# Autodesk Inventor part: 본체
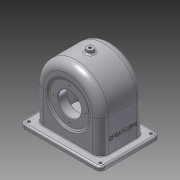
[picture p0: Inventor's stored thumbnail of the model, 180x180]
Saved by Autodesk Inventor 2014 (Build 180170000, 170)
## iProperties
Created: 2016-01
Part Number: 본체
Material: 알루미늄 6061
Document SubType Name: 판금
Designer: SCD-A15
Density: 2.71 g/cm^3
Appearance: 알루미늄 - 평지
Sheet Metal Rule: 기본값
Mass: 912.796 g
Surface Area: 1098.08 cm^2
Volume: 336.825 cm^3
Author: SCD-A15
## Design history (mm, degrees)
sketch "스케치1"
  geometry: L1 (-70, 52)-(70, 52); L2 (70, 52)-(70, -52); L3 (70, -52)-(-70, -52); L4 (-70, -52)-(-70, 52); 3 further points
  constraints: 8 end point, 2 midpoint, 2 parallel, 1 horizontal, 1 horizontal alignment, 1 perpendicular, 1 vertical alignment
  dimensions: "d0" = 140 distance of L1.start L1.end; "d1" = 104 distance of L1.end L2.end
extrude "돌출1" new body sketch "스케치1" distance "d2" = 7; taper "d3" = 0 deg
node "작업 평면1"
sketch "스케치3"
  geometry: L1 (-43, 38.5)-(43, 38.5); L2 (57, 24.5)-(57, -24.5); L3 (43, -38.5)-(-43, -38.5); L4 (-57, -24.5)-(-57, 24.5); L5 (-42, 33.5)-(42, 33.5); L6 (51, 24.5)-(51, -24.5); L7 (42, -33.5)-(-42, -33.5); L8 (-51, -24.5)-(-51, 24.5); L9 (0, 33.5)-(0, -33.5); L10 (0, 38.5)-(0, 33.5); L11 (0, -33.5)-(0, -38.5); A1 r 9 centre (-42, 24.5) between (-42, 33.5) and (-51, 24.5); A2 r 9 centre (-42, -24.5) between (-51, -24.5) and (-42, -33.5); A3 r 9 centre (42, -24.5) between (42, -33.5) and (51, -24.5); A4 r 9 centre (42, 24.5) between (51, 24.5) and (42, 33.5); A5 r 14 centre (-43, 24.5) between (-43, 38.5) and (-57, 24.5); A6 r 14 centre (-43, -24.5) between (-57, -24.5) and (-43, -38.5); A7 r 14 centre (43, -24.5) between (43, -38.5) and (57, -24.5); A8 r 14 centre (43, 24.5) between (57, 24.5) and (43, 38.5); 2 further points
  constraints: 22 end point, 16 point on circle, 16 tangent, 8 centre point, 6 equal radius, 5 midpoint, 4 parallel, 3 perpendicular, 2 horizontal, 1 collinear, 1 horizontal alignment, 1 vertical alignment
  dimensions: "d14" = 9 radius of A1; "d15" = 14 radius of A5; "d16" = 6 distance between parallel lines of L4 L8; "d17" = 6 distance between parallel lines of L2 L6; "d18" = 5 distance between parallel lines of L1 L5; "d19" = 5 distance between parallel lines of L3 L7; "d20" = 77 distance between parallel lines of L3 L1; "d21" = 114 distance between parallel lines of L4 L2
extrude "돌출2" join sketch "스케치3" stored distance "d22" = 64; taper "d23" = 0 deg
revolve "회전4" stored, may be unused: angle "d116" = 90 deg
sketch "스케치18"
  geometry: L1 (-27, 7)-(113, 7) reference; C1 r 31 at (43, -53); A1 r 43 centre (43, -57) between (0, -57) and (86, -57) reference; 1 further point
  constraints: 1 centre point, 1 vertical alignment
  dimensions: "d117" = 62 diameter of C1; "d118" = 60 distance from line of L1 C1.centre
extrude "돌출5" join sketch "스케치18" distance "d119" = 10; taper "d120" = 0 deg
sketch "스케치19"
  geometry: L1 (-38.5, 60)-(33.5, 60); L2 (-38.5, 64)-(-38.5, 107) reference; L3 (-38.5, 64)-(-38.5, 7) reference; L4 (33.5, 64)-(33.5, 7) reference; L5 (33.5, 64)-(33.5, 106) reference; L6 (-35.5, 60)-(-35.5, 94.899); L7 (-19.5, 60)-(-19.5, 88); L8 (-24.729, 106)-(33.5, 106); L9 (-35.5, 80)-(-19.5, 80); L10 (-19.5, 88)-(-33.5, 99.747); L11 (-35.5, 94.899)-(-38.5, 97.416); L12 (-33.5, 99.747)-(-33.5, 106); L13 (-33.5, 106)-(-24.729, 106); L14 (33.5, 106)-(33.5, 60); L15 (-33.5, 99.747)-(-35.5, 94.899); 1 further point
  constraints: 22 end point, 7 point on line, 4 parallel, 2 perpendicular, 1 collinear, 1 horizontal
  dimensions: "d142" = 3 distance between parallel lines of L2 L6; "d143" = 5 distance between parallel lines of L2 L12; "d144" = 56 diameter of L7.end L1; "d146" = 16 distance between parallel lines of L6 L7; "d148" = 50 deg angle of L7 L10; "d150" = 5 distance between parallel lines of L10 L11; "d151" = 40 diameter of L9 L1
revolve "회전7" stored, may be unused: angle "d153" = 90 deg
node "작업 평면5"
  node "작업 평면4"
sketch "스케치24"
  geometry: C1 r 6 at (0, 0); 1 further point
  constraints: 1 centre point, 1 coincident
  dimensions: "d155" = 12 diameter of C1
extrude "돌출6" join sketch "스케치24" stored distance "d156" = 5; taper "d157" = 0 deg
revolve "회전8" stored, may be unused: angle "d158" = 90 deg
hole "구멍6" diameter "d161" = 40; stored, may be unused: countersink angle "d165" = 90 deg, drill point angle "d167" = 0 deg; dims "d159" = 10, "d160" = 10, "d162" = 6, "d163" = 4, "d164" = 2, "d166" = 5
sketch "스케치25"
  geometry: L1 (7, 76.5)-(7, -27.5) reference; L2 (-57, -14)-(0, -14) reference; 2 further points
  constraints: 1 other
  dimensions: "d168" = 30 distance from line of point (-23, 24.5) L1; "d169" = 38.5 distance from line of L2 point (-23, 24.5)
feature "엠보싱2" sketch "스케치25" dims "d14" = 9, "d15" = 14, "d16" = 6, "d17" = 6, "d18" = 5, "d19" = 5, "d20" = 77, "d21" = 114, "d170" = 0.5, "d171" = 0
sketch "스케치27" dims "d172" = 56
  geometry: C1 r 34.899 at (0, 0) reference; 3 further points
  constraints: 1 coincident, 1 vertical alignment, 2 other
hole "구멍7" sketch "스케치27" at (0, 28) diameter "d173" = 2.459; stored, may be unused: countersink angle "d177" = 90 deg, drill point angle "d179" = 118 deg; dims "d174" = 7, "d175" = 4, "d176" = 2, "d178" = 9
sketch "스케치28" dims "d183" = 48
  geometry: C1 r 31 at (0, 0) reference; 3 further points
  constraints: 1 coincident, 1 vertical alignment, 2 other
hole "구멍8" sketch "스케치28" at (0, 24) diameter "d184" = 2.459; stored, may be unused: countersink angle "d188" = 90 deg, drill point angle "d190" = 118 deg; dims "d185" = 6, "d186" = 4, "d187" = 2, "d189" = 8
hole "구멍9" diameter "d196" = 40; stored, may be unused: countersink angle "d200" = 90 deg, drill point angle "d202" = 0 deg; dims "d194" = 10, "d195" = 10, "d197" = 6, "d198" = 4, "d199" = 2, "d201" = 32
fillet "모깎기6" dims "d203" = 8
sketch "스케치29"
  geometry: A1 r 8 centre (-62, 44) between (-62, 52) and (-70, 44) reference; A2 r 8 centre (-62, -44) between (-70, -44) and (-62, -52) reference; A3 r 8 centre (62, -44) between (62, -52) and (70, -44) reference; A4 r 8 centre (62, 44) between (70, 44) and (62, 52) reference; 1 further point
hole "구멍10" sketch "스케치29" at (-62, -44), (62, -44), (62, 44), (-62, 44) diameter "d204" = 5; stored, may be unused: countersink angle "d208" = 90 deg, drill point angle "d210" = 0 deg; dims "d205" = 6, "d206" = 4, "d207" = 2, "d209" = 32
hole "구멍11" diameter "d213" = 4.459; stored, may be unused: countersink angle "d217" = 90 deg, drill point angle "d219" = 0 deg; dims "d211" = 10, "d212" = 10, "d214" = 6, "d215" = 4, "d216" = 2, "d218" = 46.5
fillet "모깎기7" dims "d220" = 1
fillet "모깎기8" dims "d221" = 3
fillet "모깎기9" dims "d222" = 3
chamfer "모따기1" distance "d223" = 1; stored, may be unused: second distance "d224" = 2, angle "d225" = 45 deg
chamfer "모따기2" distance "d226" = 1; stored, may be unused: second distance "d227" = 2, angle "d228" = 45 deg
chamfer "모따기3" distance "d229" = 1; stored, may be unused: second distance "d230" = 2, angle "d231" = 45 deg
fillet "모깎기10" dims "d232" = 3
sketch "스케치30"
  geometry: 1 further point
node "솔리드1"
pattern_circular "원형 패턴3" dims angle "d181" = 360 deg
pattern_circular "원형 패턴4" dims angle "d192" = 360 deg
other parameters: "d13" = 57, "K계수" = 4.4, "BendRadius" = 0.5 (derived), "BendReliefWidth" = 0.5 (derived), "BendReliefDepth" = 0.25 (derived), "CornerReliefSize" = 2 (derived), "SeamGap" = 0.01, "MinimumRemnant" = 1 (derived), "TransitionRadius" = 0.5 (= BendRadius), "d132" = 50 deg, "d154" = 6
